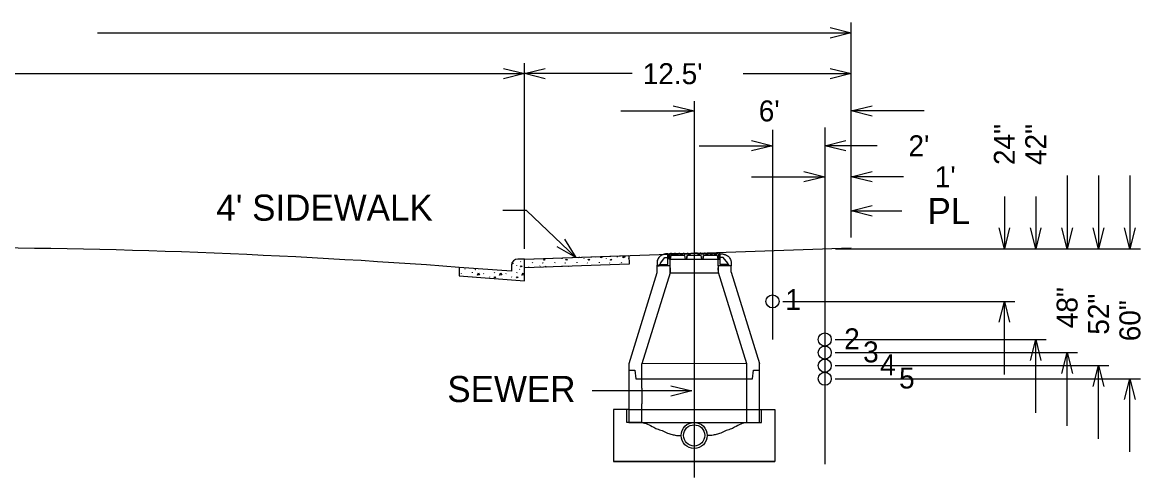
# Model space of a CAD drawing. Extents: x 524397 to 525117, y 3701341 to 3701821.
# Drawn here: x 524798.7 to 524884.3, y 3701459.7 to 3701494.6 of the extents above; entities that cross this region are included whole.
import ezdxf

# ---------------------------------------------------------------- set-up
doc = ezdxf.new("R2010")
doc.units = 0
doc.layers.add('Level 11', color=7, linetype='Continuous')

msp = doc.modelspace()

# ---------------------------------------------------------------- linework, layer by layer
at = {"layer": 'Level 11'}
for p, q in [((524804.466, 3701493.774), (524862.143, 3701493.774)), ((524860.542, 3701494.175), (524862.143, 3701493.774)), ((524862.143, 3701493.774), (524860.542, 3701493.374)), ((524862.143, 3701478.122), (524862.143, 3701494.575)), ((524837.143, 3701477.25), (524837.143, 3701491.449)), ((524862.143, 3701478.122), (524862.143, 3701491.449)), ((524794.796, 3701490.649), (524837.143, 3701490.649)), ((524835.542, 3701491.049), (524837.143, 3701490.649)), ((524837.143, 3701490.649), (524835.542, 3701490.249)), ((524837.143, 3701490.649), (524838.744, 3701491.049)), ((524845.401, 3701490.649), (524837.143, 3701490.649)), ((524838.744, 3701490.249), (524837.143, 3701490.649)), ((524853.885, 3701490.649), (524862.143, 3701490.649)), ((524860.542, 3701491.049), (524862.143, 3701490.649)), ((524862.143, 3701490.649), (524860.542, 3701490.249)), ((524844.525, 3701487.799), (524850.129, 3701487.799)), ((524848.528, 3701488.199), (524850.129, 3701487.799)), ((524850.129, 3701487.799), (524848.528, 3701487.399)), ((524850.129, 3701488.552), (524850.129, 3701459.733)), ((524862.143, 3701487.799), (524863.744, 3701488.199)), ((524867.746, 3701487.799), (524862.143, 3701487.799)), ((524863.744, 3701487.399), (524862.143, 3701487.799)), ((524856.129, 3701486.359), (524856.129, 3701470.298)), ((524860.129, 3701486.535), (524860.129, 3701460.774)), ((524854.528, 3701485.532), (524856.129, 3701485.131)), ((524860.129, 3701485.131), (524861.73, 3701485.532)), ((524850.525, 3701485.131), (524856.129, 3701485.131)), ((524856.129, 3701485.131), (524854.528, 3701484.731)), ((524864.132, 3701485.131), (524860.129, 3701485.131)), ((524861.73, 3701484.731), (524860.129, 3701485.131)), ((524854.525, 3701482.763), (524860.129, 3701482.763)), ((524858.528, 3701483.163), (524860.129, 3701482.763)), ((524860.129, 3701482.763), (524858.528, 3701482.363)), ((524862.143, 3701482.763), (524863.744, 3701483.163)), ((524866.145, 3701482.763), (524862.143, 3701482.763)), ((524863.744, 3701482.363), (524862.143, 3701482.763)), ((524878.672, 3701482.856), (524878.672, 3701477.252)), ((524881.073, 3701482.856), (524881.073, 3701477.252)), ((524883.474, 3701482.856), (524883.474, 3701477.252)), ((524873.869, 3701481.255), (524873.869, 3701477.252)), ((524876.27, 3701481.255), (524876.27, 3701477.252)), ((524837.303, 3701480.187), (524835.498, 3701480.187)), ((524841.082, 3701476.576), (524837.303, 3701480.187)), ((524862.146, 3701480.15), (524863.747, 3701480.55)), ((524862.146, 3701480.15), (524866.022, 3701480.15)), ((524863.747, 3701479.75), (524862.146, 3701480.15)), ((524873.869, 3701477.252), (524873.469, 3701478.853)), ((524874.269, 3701478.853), (524873.869, 3701477.252)), ((524876.27, 3701477.252), (524875.87, 3701478.853)), ((524876.67, 3701478.853), (524876.27, 3701477.252)), ((524878.672, 3701477.252), (524878.271, 3701478.853)), ((524879.072, 3701478.853), (524878.672, 3701477.252)), ((524881.073, 3701477.252), (524880.673, 3701478.853)), ((524881.473, 3701478.853), (524881.073, 3701477.252)), ((524883.474, 3701477.252), (524883.074, 3701478.853)), ((524883.875, 3701478.853), (524883.474, 3701477.252)), ((524840.201, 3701477.971), (524841.082, 3701476.576)), ((524837.143, 3701476.449), (524862.143, 3701477.322)), ((524837.143, 3701476.449), (524845.138, 3701476.728)), ((524841.082, 3701476.576), (524839.648, 3701477.393)), ((524845.138, 3701476.728), (524845.161, 3701476.069)), ((524848.13, 3701476.868), (524848.13, 3701476.868)), ((524848.13, 3701476.868), (524848.214, 3701476.868)), ((524848.13, 3701476.576), (524848.13, 3701476.868)), ((524848.213, 3701476.451), (524848.214, 3701476.868)), ((524848.255, 3701476.868), (524848.255, 3701476.451)), ((524848.297, 3701476.868), (524848.255, 3701476.868)), ((524848.297, 3701476.868), (524848.313, 3701476.909)), ((524848.297, 3701476.451), (524848.348, 3701476.743)), ((524848.313, 3701476.909), (524848.375, 3701476.909)), ((524849.411, 3701476.743), (524848.348, 3701476.743)), ((524848.39, 3701476.868), (524848.375, 3701476.909)), ((524848.621, 3701476.868), (524848.39, 3701476.868)), ((524848.621, 3701476.868), (524848.636, 3701476.909)), ((524848.636, 3701476.909), (524848.696, 3701476.909)), ((524848.711, 3701476.868), (524848.696, 3701476.909)), ((524848.937, 3701476.868), (524848.711, 3701476.868)), ((524848.937, 3701476.868), (524848.952, 3701476.909)), ((524848.952, 3701476.909), (524849.02, 3701476.909)), ((524849.035, 3701476.868), (524849.02, 3701476.909)), ((524849.265, 3701476.868), (524849.035, 3701476.868)), ((524849.265, 3701476.868), (524849.28, 3701476.909)), ((524849.28, 3701476.909), (524849.345, 3701476.909)), ((524849.36, 3701476.868), (524849.345, 3701476.909)), ((524849.587, 3701476.868), (524849.36, 3701476.868)), ((524849.462, 3701476.451), (524849.411, 3701476.743)), ((524849.546, 3701476.451), (524849.598, 3701476.743)), ((524849.587, 3701476.868), (524849.602, 3701476.909)), ((524850.66, 3701476.743), (524849.598, 3701476.743)), ((524849.602, 3701476.909), (524849.661, 3701476.909)), ((524849.676, 3701476.868), (524849.661, 3701476.909)), ((524849.862, 3701476.868), (524849.676, 3701476.868)), ((524849.862, 3701476.868), (524849.878, 3701476.909)), ((524849.878, 3701476.909), (524850.129, 3701476.909)), ((524850.38, 3701476.909), (524850.129, 3701476.909)), ((524850.395, 3701476.868), (524850.38, 3701476.909)), ((524850.582, 3701476.868), (524850.395, 3701476.868)), ((524850.582, 3701476.868), (524850.597, 3701476.909)), ((524850.655, 3701476.909), (524850.597, 3701476.909)), ((524850.671, 3701476.868), (524850.655, 3701476.909)), ((524850.712, 3701476.451), (524850.66, 3701476.743)), ((524850.898, 3701476.868), (524850.671, 3701476.868)), ((524850.795, 3701476.451), (524850.846, 3701476.743)), ((524851.909, 3701476.743), (524850.846, 3701476.743)), ((524850.898, 3701476.868), (524850.913, 3701476.909)), ((524850.978, 3701476.909), (524850.913, 3701476.909)), ((524850.993, 3701476.868), (524850.978, 3701476.909)), ((524851.222, 3701476.868), (524850.993, 3701476.868)), ((524851.222, 3701476.868), (524851.237, 3701476.909)), ((524851.305, 3701476.909), (524851.237, 3701476.909)), ((524851.32, 3701476.868), (524851.305, 3701476.909)), ((524851.547, 3701476.868), (524851.32, 3701476.868)), ((524851.547, 3701476.868), (524851.562, 3701476.909)), ((524851.621, 3701476.909), (524851.562, 3701476.909)), ((524851.636, 3701476.868), (524851.621, 3701476.909)), ((524851.868, 3701476.868), (524851.636, 3701476.868)), ((524851.69, 3701476.868), (524851.69, 3701476.743)), ((524851.815, 3701476.868), (524851.815, 3701476.743)), ((524851.868, 3701476.868), (524851.883, 3701476.909)), ((524851.945, 3701476.909), (524851.883, 3701476.909)), ((524851.961, 3701476.451), (524851.909, 3701476.743)), ((524851.96, 3701476.868), (524851.945, 3701476.909)), ((524852.002, 3701476.868), (524851.96, 3701476.868)), ((524852.002, 3701476.868), (524852.002, 3701476.451)), ((524852.044, 3701476.451), (524852.044, 3701476.868)), ((524852.128, 3701476.868), (524852.044, 3701476.868)), ((524852.128, 3701476.576), (524852.128, 3701476.868)), ((524860.943, 3701477.252), (524874.669, 3701477.252)), ((524860.943, 3701477.252), (524877.071, 3701477.252)), ((524860.943, 3701477.252), (524879.472, 3701477.252)), ((524860.943, 3701477.252), (524881.873, 3701477.252)), ((524860.943, 3701477.252), (524884.275, 3701477.252)), ((524836.143, 3701475.524), (524832.143, 3701475.826)), ((524832.143, 3701475.826), (524832.143, 3701475.165)), ((524836.143, 3701475.987), (524836.143, 3701475.524)), ((524836.532, 3701476.001), (524836.535, 3701475.969)), ((524837.143, 3701476.449), (524836.63, 3701476.449)), ((524836.63, 3701476.449), (524836.643, 3701476.449)), ((524836.849, 3701476.236), (524836.863, 3701476.268)), ((524837.143, 3701474.787), (524837.143, 3701476.449)), ((524837.143, 3701475.789), (524837.143, 3701476.449)), ((524845.161, 3701476.069), (524837.143, 3701475.789)), ((524837.488, 3701475.838), (524837.502, 3701475.87)), ((524837.775, 3701476.183), (524837.79, 3701476.215)), ((524838.299, 3701476.489), (524838.3, 3701476.474)), ((524838.33, 3701475.92), (524838.344, 3701475.952)), ((524838.539, 3701476.183), (524838.553, 3701476.162)), ((524838.553, 3701476.175), (524838.568, 3701476.154)), ((524839.199, 3701475.861), (524839.203, 3701475.87)), ((524839.477, 3701476.183), (524839.491, 3701476.215)), ((524839.998, 3701476.506), (524840.002, 3701476.474)), ((524840.031, 3701475.92), (524840.045, 3701475.952)), ((524840.241, 3701476.183), (524840.255, 3701476.162)), ((524840.255, 3701476.175), (524840.269, 3701476.154)), ((524841.178, 3701476.183), (524841.193, 3701476.215)), ((524841.7, 3701476.506), (524841.703, 3701476.474)), ((524841.746, 3701475.95), (524841.747, 3701475.952)), ((524841.942, 3701476.183), (524841.956, 3701476.162)), ((524841.956, 3701476.175), (524841.971, 3701476.154)), ((524842.557, 3701476.595), (524842.571, 3701476.627)), ((524842.88, 3701476.183), (524842.894, 3701476.215)), ((524843.401, 3701476.506), (524843.405, 3701476.474)), ((524843.644, 3701476.183), (524843.658, 3701476.162)), ((524843.658, 3701476.175), (524843.672, 3701476.154)), ((524844.258, 3701476.595), (524844.272, 3701476.627)), ((524844.581, 3701476.183), (524844.596, 3701476.215)), ((524845.103, 3701476.506), (524845.106, 3701476.474)), ((524847.287, 3701475.951), (524847.287, 3701475.418)), ((524847.287, 3701475.951), (524847.464, 3701475.951)), ((524848.297, 3701475.951), (524847.287, 3701475.951)), ((524847.464, 3701475.951), (524847.464, 3701476.035)), ((524847.464, 3701476.035), (524847.547, 3701476.035)), ((524847.547, 3701476.139), (524847.897, 3701476.577)), ((524847.547, 3701476.035), (524847.547, 3701476.139)), ((524847.547, 3701476.035), (524848.13, 3701476.035)), ((524847.897, 3701476.577), (524848.13, 3701476.576)), ((524848.13, 3701476.035), (524848.13, 3701476.576)), ((524848.297, 3701476.451), (524848.213, 3701476.451)), ((524848.255, 3701476.451), (524852.002, 3701476.451)), ((524848.286, 3701475.419), (524848.286, 3701475.951)), ((524848.286, 3701475.785), (524848.286, 3701475.459)), ((524848.297, 3701475.951), (524848.297, 3701476.451)), ((524851.961, 3701475.951), (524851.961, 3701476.451)), ((524851.961, 3701476.451), (524852.044, 3701476.451)), ((524852.971, 3701475.951), (524851.961, 3701475.951)), ((524851.972, 3701475.951), (524851.972, 3701475.452)), ((524852.971, 3701475.951), (524851.972, 3701475.951)), ((524851.972, 3701475.618), (524851.972, 3701475.792)), ((524852.36, 3701476.577), (524852.128, 3701476.576)), ((524852.128, 3701476.035), (524852.128, 3701476.576)), ((524852.71, 3701476.035), (524852.128, 3701476.035)), ((524852.71, 3701476.139), (524852.36, 3701476.577)), ((524852.71, 3701476.035), (524852.71, 3701476.139)), ((524852.794, 3701476.035), (524852.71, 3701476.035)), ((524852.794, 3701475.951), (524852.794, 3701476.035)), ((524852.971, 3701475.951), (524852.794, 3701475.951)), ((524852.971, 3701475.452), (524852.971, 3701475.951)), ((524832.143, 3701475.165), (524837.143, 3701474.787)), ((524832.32, 3701475.333), (524832.334, 3701475.365)), ((524832.607, 3701475.678), (524832.622, 3701475.71)), ((524833.162, 3701475.415), (524833.176, 3701475.447)), ((524833.371, 3701475.678), (524833.385, 3701475.657)), ((524833.385, 3701475.67), (524833.4, 3701475.649)), ((524834.021, 3701475.333), (524834.035, 3701475.365)), ((524834.465, 3701475.106), (524834.479, 3701475.084)), ((524834.863, 3701475.415), (524834.877, 3701475.447)), ((524835.723, 3701475.333), (524835.737, 3701475.365)), ((524836.167, 3701475.106), (524836.181, 3701475.084)), ((524836.565, 3701475.415), (524836.579, 3701475.447)), ((524836.774, 3701475.678), (524836.788, 3701475.657)), ((524836.788, 3701475.67), (524836.803, 3701475.649)), ((524847.287, 3701475.418), (524845.136, 3701468.451)), ((524848.286, 3701475.419), (524846.136, 3701468.452)), ((524848.286, 3701475.419), (524851.972, 3701475.419)), ((524851.972, 3701475.452), (524854.131, 3701468.456)), ((524852.971, 3701475.452), (524855.13, 3701468.456)), ((524856.929, 3701473.222), (524874.669, 3701473.222)), ((524873.469, 3701471.621), (524873.869, 3701473.222)), ((524873.869, 3701467.619), (524873.869, 3701473.222)), ((524873.869, 3701473.222), (524874.269, 3701471.621)), ((524860.929, 3701470.302), (524877.071, 3701470.302)), ((524875.87, 3701468.701), (524876.27, 3701470.302)), ((524876.27, 3701464.698), (524876.27, 3701470.302)), ((524876.27, 3701470.302), (524876.67, 3701468.701)), ((524860.929, 3701469.302), (524879.472, 3701469.302)), ((524878.271, 3701467.701), (524878.672, 3701469.302)), ((524878.672, 3701463.698), (524878.672, 3701469.302)), ((524878.672, 3701469.302), (524879.072, 3701467.701)), ((524845.136, 3701468.451), (524845.136, 3701467.29)), ((524845.136, 3701468.158), (524845.136, 3701467.956)), ((524854.131, 3701468.456), (524846.136, 3701468.452)), ((524846.136, 3701467.29), (524846.136, 3701468.452)), ((524846.136, 3701467.956), (524846.136, 3701468.158)), ((524854.131, 3701468.456), (524854.131, 3701467.29)), ((524854.131, 3701468.456), (524854.131, 3701467.956)), ((524854.131, 3701468.158), (524854.131, 3701467.956)), ((524854.131, 3701468.158), (524854.131, 3701467.956)), ((524855.13, 3701467.956), (524855.13, 3701468.456)), ((524855.13, 3701467.956), (524855.13, 3701468.456)), ((524855.13, 3701463.959), (524855.13, 3701468.158)), ((524860.929, 3701468.302), (524881.873, 3701468.302)), ((524880.673, 3701466.701), (524881.073, 3701468.302)), ((524881.073, 3701462.698), (524881.073, 3701468.302)), ((524881.073, 3701468.302), (524881.473, 3701466.701)), ((524845.136, 3701467.956), (524845.594, 3701467.956)), ((524845.136, 3701467.956), (524845.594, 3701467.956)), ((524845.136, 3701467.956), (524845.136, 3701466.569)), ((524845.136, 3701467.568), (524845.136, 3701463.959)), ((524845.594, 3701467.956), (524845.677, 3701467.29)), ((524845.594, 3701467.956), (524845.677, 3701467.29)), ((524845.677, 3701467.29), (524846.136, 3701467.29)), ((524845.677, 3701467.29), (524846.136, 3701467.29)), ((524846.136, 3701466.569), (524846.136, 3701467.956)), ((524846.136, 3701467.29), (524854.131, 3701467.29)), ((524846.136, 3701467.29), (524854.131, 3701467.29)), ((524854.131, 3701467.956), (524854.131, 3701463.959)), ((524854.131, 3701467.956), (524854.131, 3701463.959)), ((524854.131, 3701467.29), (524854.589, 3701467.29)), ((524854.131, 3701467.29), (524854.589, 3701467.29)), ((524854.589, 3701467.29), (524854.672, 3701467.956)), ((524854.589, 3701467.29), (524854.672, 3701467.956)), ((524854.672, 3701467.956), (524855.13, 3701467.956)), ((524854.672, 3701467.956), (524855.13, 3701467.956)), ((524854.672, 3701467.956), (524855.13, 3701467.956)), ((524855.13, 3701467.29), (524855.13, 3701467.956)), ((524860.929, 3701467.302), (524884.275, 3701467.302)), ((524883.074, 3701465.701), (524883.474, 3701467.302)), ((524883.474, 3701461.698), (524883.474, 3701467.302)), ((524883.474, 3701467.302), (524883.875, 3701465.701)), ((524849.944, 3701466.366), (524842.327, 3701466.366)), ((524846.136, 3701466.569), (524846.136, 3701465.385)), ((524848.343, 3701466.766), (524849.944, 3701466.366)), ((524849.944, 3701466.366), (524848.343, 3701465.966)), ((524845.136, 3701464.958), (524843.97, 3701464.958)), ((524843.97, 3701464.958), (524843.97, 3701460.961)), ((524844.97, 3701463.959), (524844.97, 3701464.958)), ((524845.136, 3701464.958), (524855.13, 3701464.958)), ((524846.136, 3701463.959), (524846.136, 3701465.385)), ((524855.13, 3701464.958), (524856.296, 3701464.958)), ((524855.297, 3701463.959), (524855.297, 3701464.958)), ((524856.296, 3701464.958), (524856.296, 3701460.961)), ((524845.136, 3701463.959), (524844.97, 3701463.959)), ((524845.136, 3701463.959), (524844.97, 3701463.959)), ((524845.136, 3701463.959), (524846.136, 3701463.959)), ((524846.136, 3701463.959), (524845.136, 3701463.959)), ((524846.136, 3701463.959), (524845.136, 3701463.959)), ((524846.136, 3701463.959), (524854.131, 3701463.959)), ((524854.131, 3701463.959), (524855.13, 3701463.959)), ((524854.131, 3701463.959), (524855.13, 3701463.959)), ((524855.13, 3701463.959), (524855.297, 3701463.959)), ((524856.296, 3701460.961), (524843.97, 3701460.961)), ((524843.97, 3701460.961), (524856.296, 3701460.961))]:
    msp.add_line(p, q, dxfattribs=at)
for points in [[(524842.989, 3701476.558), (524843.002, 3701476.654)], [(524843.118, 3701476.658), (524843.144, 3701476.63), (524842.992, 3701476.56)], [(524844.69, 3701476.558), (524844.712, 3701476.713)], [(524844.763, 3701476.715), (524844.846, 3701476.63), (524844.694, 3701476.56)], [(524836.207, 3701476.195), (524836.275, 3701476.125), (524836.17, 3701476.077)], [(524836.856, 3701475.863), (524836.899, 3701475.952), (524836.97, 3701475.898), (524836.856, 3701475.863)], [(524837.143, 3701475.837), (524837.164, 3701475.79)], [(524838.621, 3701476.368), (524838.664, 3701476.457), (524838.735, 3701476.403), (524838.621, 3701476.368)], [(524838.764, 3701475.845), (524838.806, 3701475.923), (524838.839, 3701475.848)], [(524840.322, 3701476.368), (524840.365, 3701476.457), (524840.436, 3701476.403), (524840.322, 3701476.368)], [(524840.498, 3701475.906), (524840.507, 3701475.923), (524840.515, 3701475.907)], [(524841.287, 3701476.558), (524841.292, 3701476.594)], [(524841.371, 3701476.597), (524841.291, 3701476.56)], [(524842.024, 3701476.368), (524842.067, 3701476.457), (524842.138, 3701476.403), (524842.024, 3701476.368)], [(524843.725, 3701476.368), (524843.768, 3701476.457), (524843.839, 3701476.403), (524843.725, 3701476.368)], [(524833.172, 3701475.087), (524833.179, 3701475.102), (524833.203, 3701475.085)], [(524833.542, 3701475.237), (524833.638, 3701475.418), (524833.712, 3701475.251), (524833.545, 3701475.237)], [(524834.838, 3701475.013), (524834.881, 3701475.102), (524834.952, 3701475.049), (524834.838, 3701475.013)], [(524835.243, 3701475.237), (524835.339, 3701475.418), (524835.414, 3701475.251), (524835.247, 3701475.237)], [(524836.54, 3701475.013), (524836.582, 3701475.102), (524836.653, 3701475.049), (524836.54, 3701475.013)], [(524836.945, 3701475.237), (524837.041, 3701475.418), (524837.115, 3701475.251), (524836.948, 3701475.237)]]:
    msp.add_lwpolyline(points, dxfattribs=at)
for points in [[(524848.255, 3701476.868), (524848.297, 3701476.868), (524848.313, 3701476.909), (524848.375, 3701476.909), (524848.39, 3701476.868), (524848.621, 3701476.868), (524848.636, 3701476.909), (524848.696, 3701476.909), (524848.711, 3701476.868), (524848.937, 3701476.868), (524848.952, 3701476.909), (524849.02, 3701476.909), (524849.035, 3701476.868), (524849.265, 3701476.868), (524849.28, 3701476.909), (524849.345, 3701476.909), (524849.36, 3701476.868), (524849.587, 3701476.868), (524849.602, 3701476.909), (524849.661, 3701476.909), (524849.676, 3701476.868), (524849.862, 3701476.868), (524849.878, 3701476.909), (524850.38, 3701476.909), (524850.395, 3701476.868), (524850.582, 3701476.868), (524850.597, 3701476.909), (524850.655, 3701476.909), (524850.671, 3701476.868), (524850.898, 3701476.868), (524850.913, 3701476.909), (524850.978, 3701476.909), (524850.993, 3701476.868), (524851.222, 3701476.868), (524851.237, 3701476.909), (524851.305, 3701476.909), (524851.32, 3701476.868), (524851.547, 3701476.868), (524851.562, 3701476.909), (524851.621, 3701476.909), (524851.636, 3701476.868), (524851.69, 3701476.868), (524851.69, 3701476.743), (524850.846, 3701476.743), (524850.795, 3701476.451), (524850.712, 3701476.451), (524850.66, 3701476.743), (524849.598, 3701476.743), (524849.546, 3701476.451), (524849.462, 3701476.451), (524849.411, 3701476.743), (524848.348, 3701476.743), (524848.297, 3701476.451), (524848.255, 3701476.451)], [(524851.815, 3701476.868), (524851.868, 3701476.868), (524851.883, 3701476.909), (524851.945, 3701476.909), (524851.96, 3701476.868), (524852.002, 3701476.868), (524852.002, 3701476.451), (524851.961, 3701476.451), (524851.909, 3701476.743), (524851.815, 3701476.743)]]:
    msp.add_lwpolyline(points, close=True, dxfattribs=at)
for centre, radius in [((524856.129, 3701473.222), 0.5), ((524860.129, 3701470.302), 0.5), ((524860.129, 3701469.302), 0.5), ((524860.129, 3701468.302), 0.5), ((524860.129, 3701467.302), 0.5), ((524850.133, 3701462.96), 0.999), ((524850.133, 3701462.96), 0.814)]:
    msp.add_circle(centre, radius, dxfattribs=at)
for centre, radius, start, end in [((524792.143, 3700946.025), 531.309, 85.68236, 94.31764), ((524836.636, 3701475.955), 0.494, 89.23325, 176.29205)]:
    msp.add_arc(centre, radius, start, end, dxfattribs=at)
for points in [[(524848.13, 3701476.868), (524848.057, 3701476.867), (524847.978, 3701476.856), (524847.909, 3701476.844), (524847.85, 3701476.832), (524847.786, 3701476.804), (524847.728, 3701476.791), (524847.585, 3701476.711), (524847.481, 3701476.626), (524847.39, 3701476.507), (524847.314, 3701476.343), (524847.293, 3701476.111), (524847.287, 3701475.951)], [(524852.128, 3701476.868), (524852.2, 3701476.867), (524852.28, 3701476.856), (524852.348, 3701476.844), (524852.407, 3701476.832), (524852.471, 3701476.804), (524852.53, 3701476.791), (524852.673, 3701476.711), (524852.776, 3701476.626), (524852.867, 3701476.507), (524852.944, 3701476.343), (524852.964, 3701476.111), (524852.971, 3701475.951)], [(524846.136, 3701463.959), (524846.55, 3701463.834), (524847.053, 3701463.583), (524847.369, 3701463.436), (524847.788, 3701463.289), (524848.187, 3701463.101), (524848.523, 3701463.017), (524848.859, 3701462.954), (524849.134, 3701462.959)], [(524854.131, 3701463.959), (524853.717, 3701463.834), (524853.213, 3701463.583), (524852.898, 3701463.436), (524852.478, 3701463.289), (524852.079, 3701463.101), (524851.743, 3701463.017), (524851.407, 3701462.954), (524851.133, 3701462.959)]]:
    msp.add_spline(points, degree=3, dxfattribs=at)

# ---------------------------------------------------------------- texts
for s, height, p in [("12.5'", 1.601, (524846.201, 3701489.848)), ("6'", 1.601, (524855.077, 3701486.998)), ("2'", 1.601, (524866.533, 3701484.33)), ("1'", 1.601, (524868.547, 3701481.962)), ("4' SIDEWALK", 2, (524813.568, 3701479.397)), ('PL', 2, (524867.992, 3701479.132)), ('1', 1.601, (524857.108, 3701472.557)), ('2', 1.601, (524861.614, 3701469.557)), ('3', 1.601, (524863.064, 3701468.557)), ('4', 1.601, (524864.363, 3701467.557)), ('5', 1.601, (524865.813, 3701466.557)), ('SEWER', 2, (524831.247, 3701465.516))]:
    msp.add_text(s, height=height, dxfattribs=at).set_placement(p)
for s, p in [('24"', (524874.669, 3701483.656)), ('42"', (524877.071, 3701483.656)), ('48"', (524879.472, 3701471.171)), ('52"', (524881.874, 3701470.671)), ('60"', (524884.275, 3701470.171))]:
    msp.add_text(s, height=1.601, rotation=90, dxfattribs=at).set_placement(p)

doc.saveas('drawing.dxf')
